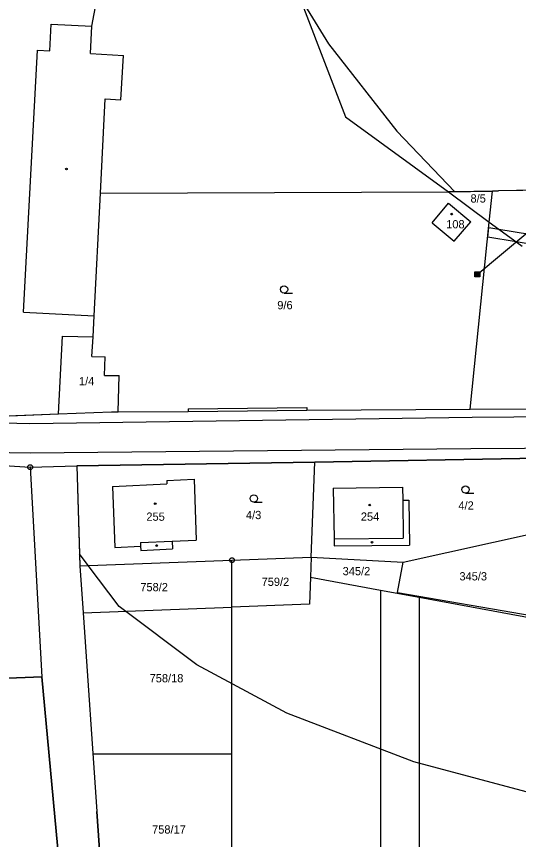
# Model space of a CAD drawing. Extents: x -725765 to -723182, y -1052705 to -1049154.
# Drawn here: x -724596 to -724492.6, y -1051081 to -1050911.3 of the extents above; entities that cross this region are included whole.
import ezdxf

# ---------------------------------------------------------------- set-up
doc = ezdxf.new("R2010")
doc.units = 0
for name, color, linetype in [('Vrstva 1', 7, 'Continuous'), ('Vrstva 12', 7, 'Continuous'), ('Vrstva 18', 7, 'Continuous'), ('Vrstva 19', 7, 'Continuous'), ('Vrstva 25', 7, 'Continuous'), ('Vrstva 27', 7, 'Continuous'), ('Vrstva 4', 7, 'Continuous'), ('Vrstva 52', 7, 'Continuous')]:
    doc.layers.add(name, color=color, linetype=linetype)

msp = doc.modelspace()

# ---------------------------------------------------------------- linework, layer by layer
at = {"layer": 'Vrstva 1'}
msp.add_line((-724580.29, -1051063.32), (-724551.61, -1051063.32), dxfattribs=at)
for points in [[(-724569.4, -1050824.59), (-724528.23, -1050932)], [(-724580.49, -1050913.34), (-724578.03, -1050900.23)], [(-724580.78, -1050918.96), (-724580.49, -1050913.34)], [(-724580.78, -1050918.96), (-724573.99, -1050919.38)], [(-724574.54, -1050928.48), (-724573.99, -1050919.38)], [(-724578.73, -1050947.76), (-724577.74, -1050928.32)], [(-724577.74, -1050928.32), (-724574.54, -1050928.48)], [(-724528.23, -1050932), (-724507.01, -1050947.49)], [(-724507.01, -1050947.49), (-724497.92, -1050947.32)], [(-724498.57, -1050953.71), (-724497.92, -1050947.32)], [(-724497.92, -1050947.32), (-724496.66, -1050947.3)], [(-724486.65, -1050947.12), (-724496.66, -1050947.3)], [(-724580.02, -1050973.02), (-724578.73, -1050947.76)], [(-724578.73, -1050947.76), (-724507.01, -1050947.49)], [(-724507.01, -1050947.49), (-724498.57, -1050953.71)], [(-724510.35, -1050953.86), (-724506.96, -1050949.82)], [(-724506.96, -1050949.82), (-724502.37, -1050953.65)], [(-724510.35, -1050953.86), (-724505.8, -1050957.68)], [(-724505.8, -1050957.68), (-724502.37, -1050953.65)], [(-724502.49, -1050992.29), (-724498.57, -1050953.71)], [(-724498.57, -1050953.71), (-724491.8, -1050958.69)], [(-724580.23, -1050977.37), (-724580.02, -1050973.02)], [(-724587.33, -1050993.27), (-724586.52, -1050977.23)], [(-724586.52, -1050977.23), (-724580.23, -1050977.37)], [(-724580.48, -1050981.41), (-724580.23, -1050977.37)], [(-724580.48, -1050981.41), (-724577.76, -1050981.47)], [(-724577.9, -1050985.32), (-724577.76, -1050981.47)], [(-724577.9, -1050985.32), (-724574.88, -1050985.32)], [(-724575.09, -1050992.84), (-724574.88, -1050985.32)], [(-724610.32, -1050994.17), (-724587.33, -1050993.27)], [(-724587.33, -1050993.27), (-724576.41, -1050992.85)], [(-724576.41, -1050992.85), (-724575.09, -1050992.84)], [(-724575.09, -1050992.84), (-724560.62, -1050992.78)], [(-724560.62, -1050992.78), (-724536.18, -1050992.47)], [(-724536.18, -1050992.47), (-724502.49, -1050992.29)], [(-724502.49, -1050992.29), (-724456.42, -1050992.05)], [(-724638.34, -1051001.35), (-724593.19, -1051004.26)], [(-724583.61, -1051003.99), (-724534.5, -1051003.23)], [(-724535.28, -1051022.81), (-724534.5, -1051003.23)], [(-724534.5, -1051003.23), (-724488.46, -1051002.37)], [(-724593.19, -1051004.26), (-724583.61, -1051003.99)], [(-724593.19, -1051004.26), (-724590.83, -1051047.49)], [(-724583.61, -1051003.99), (-724582.95, -1051024.61)], [(-724565.05, -1051006.98), (-724559.43, -1051006.7)], [(-724559.43, -1051006.7), (-724558.97, -1051019.28)], [(-724576.23, -1051008.23), (-724565.02, -1051007.68)], [(-724576.23, -1051008.23), (-724575.73, -1051020.79)], [(-724565.05, -1051006.98), (-724565.02, -1051007.68)], [(-724530.74, -1051008.57), (-724516.45, -1051008.39)], [(-724516.45, -1051008.39), (-724516.41, -1051011.06)], [(-724530.74, -1051008.57), (-724530.55, -1051019.04)], [(-724516.41, -1051011.06), (-724515.13, -1051011.04)], [(-724515.13, -1051011.04), (-724515.01, -1051020.31)], [(-724516.35, -1051023.82), (-724488.68, -1051017.73)], [(-724570.47, -1051019.76), (-724563.95, -1051019.49)], [(-724570.47, -1051019.76), (-724570.43, -1051020.54)], [(-724563.95, -1051019.49), (-724558.97, -1051019.28)], [(-724530.55, -1051019.04), (-724530.52, -1051020.48)], [(-724530.52, -1051020.48), (-724515.01, -1051020.31)], [(-724575.73, -1051020.79), (-724570.43, -1051020.54)], [(-724582.95, -1051024.61), (-724551.61, -1051023.43)], [(-724551.61, -1051023.43), (-724535.28, -1051022.81)], [(-724551.61, -1051033.11), (-724551.61, -1051023.43)], [(-724535.28, -1051022.81), (-724535.44, -1051026.94)], [(-724535.28, -1051022.81), (-724516.35, -1051023.82)], [(-724517.5, -1051030.06), (-724516.35, -1051023.82)], [(-724582.95, -1051024.61), (-724582.3, -1051034.26)], [(-724535.44, -1051026.94), (-724535.66, -1051032.51)], [(-724535.44, -1051026.94), (-724521.01, -1051029.6)], [(-724521.01, -1051029.6), (-724520.99, -1051292.58)], [(-724521.01, -1051029.6), (-724513.05, -1051031.07)], [(-724517.53, -1051030.24), (-724517.5, -1051030.06)], [(-724517.53, -1051030.24), (-724513.05, -1051031.07)], [(-724513.05, -1051031.07), (-724513.03, -1051301.26)], [(-724513.05, -1051031.07), (-724489.62, -1051035.39)], [(-724582.3, -1051034.26), (-724551.61, -1051033.11)], [(-724535.66, -1051032.51), (-724551.61, -1051033.11)], [(-724551.59, -1051256.55), (-724551.61, -1051033.11)], [(-724582.3, -1051034.26), (-724579.46, -1051075.24)], [(-724661.75, -1051050.29), (-724590.83, -1051047.49)], [(-724590.83, -1051047.49), (-724580.43, -1051159.22)], [(-724574.13, -1051152.55), (-724579.46, -1051075.24)]]:
    msp.add_lwpolyline(points, dxfattribs=at)
at = {"layer": 'Vrstva 12'}
msp.add_lwpolyline([(-724501.06, -1050964.51), (-724455.97, -1050926.8)], dxfattribs=at)
at = {"layer": 'Vrstva 25'}
for points in [[(-724501.56, -1050964.01), (-724500.56, -1050964.01), (-724500.56, -1050965.01), (-724501.56, -1050965.01), (-724501.56, -1050964.01)], [(-724501.36, -1050964.21), (-724500.76, -1050964.21), (-724500.76, -1050964.81), (-724501.36, -1050964.81), (-724501.36, -1050964.21)], [(-724501.16, -1050964.41), (-724500.96, -1050964.41), (-724500.96, -1050964.61), (-724501.16, -1050964.61), (-724501.16, -1050964.41)], [(-724540.88, -1050968.35), (-724539.13, -1050968.35)], [(-724503.49, -1051009.62), (-724501.74, -1051009.62)], [(-724547.11, -1051011.46), (-724545.36, -1051011.46)]]:
    msp.add_lwpolyline(points, dxfattribs=at)
for centre, radius in [((-724585.72, -1050942.77), 0.175), ((-724506.33, -1050952.07), 0.175), ((-724540.88, -1050967.6), 0.75), ((-724593.19, -1051004.26), 0.5), ((-724593.19, -1051004.26), 0.032), ((-724503.49, -1051008.87), 0.75), ((-724547.11, -1051010.71), 0.75), ((-724567.42, -1051011.78), 0.175), ((-724523.23, -1051012.06), 0.175), ((-724567.13, -1051020.41), 0.175), ((-724522.74, -1051019.73), 0.175), ((-724551.61, -1051023.43), 0.5), ((-724551.61, -1051023.43), 0.032)]:
    msp.add_circle(centre, radius, dxfattribs=at)
at = {"layer": 'Vrstva 27'}
for points in [[(-724498.89, -1050956.81), (-724498.68, -1050954.82)], [(-724498.68, -1050954.82), (-724496.59, -1050955.16)], [(-724496.59, -1050955.16), (-724467.96, -1050959.88)], [(-724493.05, -1050957.77), (-724498.89, -1050956.81)], [(-724468.32, -1050961.84), (-724493.05, -1050957.77)]]:
    msp.add_lwpolyline(points, dxfattribs=at)
at = {"layer": 'Vrstva 4'}
for points in [[(-724589.14, -1050918.44), (-724588.87, -1050912.92)], [(-724588.87, -1050912.92), (-724580.49, -1050913.34)], [(-724594.58, -1050972.27), (-724591.69, -1050918.28)], [(-724591.69, -1050918.28), (-724589.14, -1050918.44)], [(-724594.58, -1050972.27), (-724580.02, -1050973.02)], [(-724560.63, -1050992.23), (-724536.19, -1050991.92)], [(-724560.63, -1050992.23), (-724560.62, -1050992.78)], [(-724536.19, -1050991.92), (-724536.18, -1050992.47)], [(-724649.31, -1050993.81), (-724593.29, -1050995.25)], [(-724593.29, -1050995.25), (-724502.1, -1050993.92)], [(-724502.1, -1050993.92), (-724424.8, -1050993.31)], [(-724502.39, -1051000.4), (-724424.9, -1050999.89)], [(-724648.71, -1051000.4), (-724593.2, -1051001.28)], [(-724593.2, -1051001.28), (-724502.39, -1051000.4)], [(-724516.41, -1051011.06), (-724516.31, -1051018.89)], [(-724563.95, -1051019.49), (-724563.88, -1051021.1)], [(-724530.55, -1051019.04), (-724516.31, -1051018.89)], [(-724570.43, -1051020.54), (-724570.39, -1051021.43)], [(-724570.39, -1051021.43), (-724563.88, -1051021.1)], [(-724517.5, -1051030.06), (-724489.51, -1051034.92)]]:
    msp.add_lwpolyline(points, dxfattribs=at)
at = {"layer": 'Vrstva 52'}
for points in [[(-724733.3, -1050722.26), (-724731.38, -1050724), (-724718.63, -1050730), (-724709.97, -1050732.26), (-724695.63, -1050736), (-724671.88, -1050741), (-724646.63, -1050753), (-724630.63, -1050761), (-724607.63, -1050779), (-724593.38, -1050794), (-724585.13, -1050806), (-724577.38, -1050827), (-724569.81, -1050845), (-724556, -1050870), (-724545.81, -1050894), (-724531.69, -1050917), (-724517.63, -1050935), (-724505.66, -1050947.46)], [(-724505.66, -1050947.46), (-724507.01, -1050947.49), (-724498.57, -1050953.71), (-724492.05, -1050958.5)], [(-724463.55, -1050946.69), (-724496.66, -1050947.3), (-724497.92, -1050947.32), (-724505.66, -1050947.46)], [(-724597.47, -1050993.67), (-724587.33, -1050993.27), (-724576.41, -1050992.85), (-724575.09, -1050992.84), (-724560.62, -1050992.78), (-724536.18, -1050992.47), (-724502.49, -1050992.29), (-724456.42, -1050992.05), (-724442.15, -1050991.98)], [(-724431.78, -1051000.16), (-724465.46, -1051001.47), (-724488.46, -1051002.37), (-724534.5, -1051003.23), (-724583.61, -1051003.99), (-724583.03, -1051022.13)], [(-724431.78, -1051000.16), (-724413.84, -1051014.31), (-724406.63, -1051020), (-724373.31, -1051046), (-724359.88, -1051058), (-724355.38, -1051067), (-724357.31, -1051075), (-724363.13, -1051081), (-724375.88, -1051085), (-724394.38, -1051085), (-724409.81, -1051081), (-724423.19, -1051078), (-724440.5, -1051076), (-724465.38, -1051075), (-724487.88, -1051072), (-724514.13, -1051065), (-724540.31, -1051055), (-724558.88, -1051045), (-724574.88, -1051033), (-724581.22, -1051024.54), (-724583.03, -1051022.13)], [(-724583.03, -1051022.13), (-724582.95, -1051024.61), (-724582.3, -1051034.26), (-724579.46, -1051075.24), (-724574.13, -1051152.55)], [(-724580.43, -1051159.22), (-724590.83, -1051047.49), (-724661.75, -1051050.29), (-724651.62, -1051161.43)]]:
    msp.add_lwpolyline(points, dxfattribs=at)

# ---------------------------------------------------------------- texts
at = {"layer": 'Vrstva 18'}
for s, p in [('8/5', (-724502.45, -1050949.69)), ('9/6', (-724542.27, -1050971.69)), ('4/2', (-724504.94, -1051013)), ('4/3', (-724548.73, -1051014.96)), ('345/2', (-724528.8, -1051026.53)), ('759/2', (-724545.5, -1051028.73)), ('345/3', (-724504.73, -1051027.6)), ('758/2', (-724570.5, -1051029.83)), ('758/18', (-724568.58, -1051048.61)), ('758/17', (-724568.07, -1051079.79))]:
    msp.add_text(s, height=1.7, dxfattribs=at).set_placement(p)
at = {"layer": 'Vrstva 19'}
for s, p in [('108', (-724507.46, -1050955.01)), ('1/4', (-724583.14, -1050987.36)), ('255', (-724569.25, -1051015.3)), ('254', (-724525.05, -1051015.29))]:
    msp.add_text(s, height=1.7, dxfattribs=at).set_placement(p)

doc.saveas('drawing.dxf')
